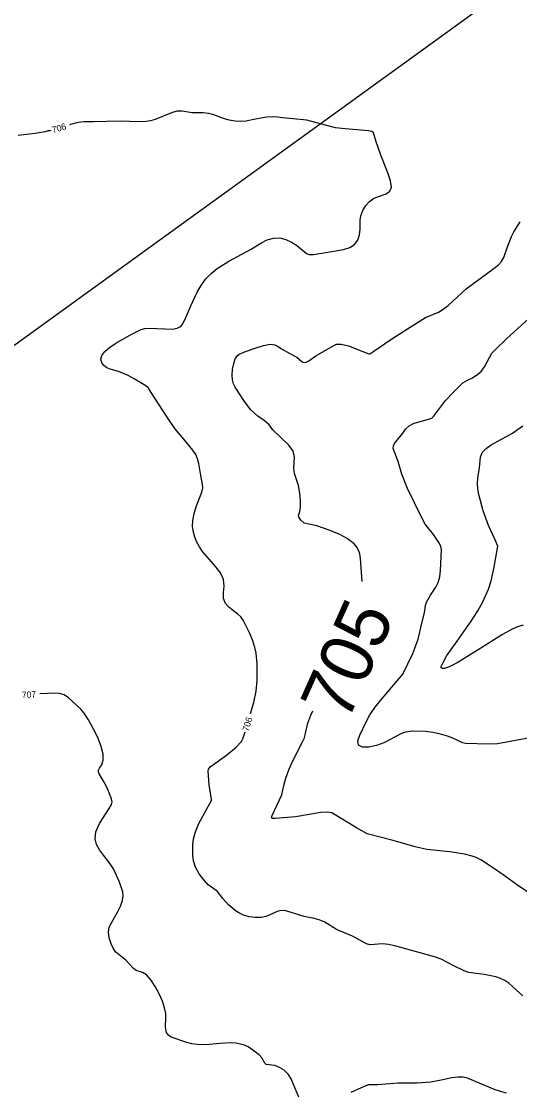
# Model space of a CAD drawing. Extents: x -291892836 to 2945206, y -477993085 to 1832792.
# Drawn here: x 1848702 to 1849014, y 544659 to 545329 of the extents above; entities that cross this region are included whole.
import ezdxf

# ---------------------------------------------------------------- set-up
doc = ezdxf.new("R2010")
doc.units = 0
for name, color, linetype in [('DT_X_Contour_Minor', 7, 'Continuous'), ('DT_X_Terrain_Ground_Line', 7, 'Continuous'), ('Level 19', 7, 'Continuous'), ('SC_Scratch1', 7, 'Continuous')]:
    doc.layers.add(name, color=color, linetype=linetype)

msp = doc.modelspace()

# ---------------------------------------------------------------- linework, layer by layer
at = {"layer": 'DT_X_Contour_Minor'}
for points in [[(1848933.23, 545229.58), (1848931.48, 545234.56), (1848927.12, 545245.56), (1848924.05, 545254.6), (1848922.57, 545259.58), (1848921.44, 545260.36), (1848919.36, 545260.82), (1848904.81, 545262.02), (1848898.8, 545262.72), (1848880.82, 545267.4), (1848872.31, 545268.27), (1848865.59, 545268.96), (1848862.55, 545269.41), (1848859.38, 545269.6), (1848855.87, 545269.38), (1848848.73, 545268.12), (1848842.54, 545266.9), (1848839.37, 545266.7), (1848835.88, 545266.93), (1848832.24, 545267.56), (1848828.75, 545268.52), (1848822.56, 545270.86), (1848819.43, 545271.68), (1848816.02, 545271.99), (1848809, 545272.19), (1848802.71, 545273.11), (1848799.51, 545273.03), (1848796.06, 545272.12), (1848785.87, 545267.93), (1848782.97, 545267.09), (1848780.33, 545266.59), (1848775.27, 545266.46), (1848764.39, 545266.89), (1848755.34, 545266.68), (1848747.31, 545266.39), (1848741.37, 545266.53), (1848737.75, 545266.03), (1848732.95, 545264.75), (1848732.27, 545264.54)], [(1848720.78, 545261.08), (1848719.93, 545260.82), (1848718.9, 545260.78), (1848717.02, 545260.24), (1848710.67, 545259.15), (1848700.11, 545257.83)], [(1848845.57, 544895.69), (1848847.69, 544902.71), (1848849.15, 544909.67), (1848849.67, 544916.5), (1848849.64, 544926.85), (1848849.02, 544933.56), (1848848.27, 544937.12), (1848846.99, 544941.19), (1848845.09, 544945.85), (1848840.98, 544954.16), (1848839.55, 544956.35), (1848837.67, 544957.99), (1848833.97, 544960.73), (1848831.92, 544962.45), (1848829.95, 544964.75), (1848828.74, 544967.72), (1848828.68, 544971.38), (1848828.99, 544975.49), (1848828.61, 544979.73), (1848826.75, 544983.84), (1848823.87, 544987.69), (1848815.55, 544997.3), (1848813.57, 545000.17), (1848811.94, 545003.12), (1848810.67, 545006.21), (1848809.78, 545009.46), (1848809.31, 545012.91), (1848809.4, 545016.69), (1848810.22, 545020.97), (1848811.81, 545025.76), (1848815.09, 545034.44), (1848815.65, 545037.17), (1848815.52, 545039.3), (1848814.5, 545044.95), (1848813.28, 545052.31), (1848812.46, 545055.33), (1848811.26, 545058.03), (1848809.42, 545060.84), (1848803.78, 545067.59), (1848798.23, 545074.28), (1848793.31, 545081.32), (1848783.41, 545096.92), (1848781.72, 545099.55), (1848780.07, 545100.95), (1848772.39, 545105.73), (1848768.96, 545107.58), (1848762.9, 545109.94), (1848757.73, 545111.49), (1848755.5, 545112.42), (1848753.69, 545113.72), (1848752.42, 545115.51), (1848751.95, 545117.68), (1848752.52, 545120.05), (1848754.33, 545122.5), (1848757.27, 545125.03), (1848761.16, 545127.68), (1848770.35, 545133.03), (1848777.05, 545136.39), (1848779.33, 545137), (1848782.05, 545137.1), (1848796.64, 545136.46), (1848799.62, 545137.14), (1848801.84, 545138.27), (1848802.97, 545139.59), (1848804.44, 545142.35), (1848808.19, 545151.21), (1848812.12, 545159.74), (1848814.59, 545163.96), (1848817.47, 545167.89), (1848820.84, 545171.45), (1848824.68, 545174.53), (1848831.96, 545179.05), (1848845.46, 545186.45), (1848852.09, 545190.47), (1848855.94, 545192.42), (1848859.92, 545193.63), (1848863.87, 545193.69), (1848867.65, 545192.76), (1848871.16, 545191.12), (1848874.29, 545189.09), (1848880.63, 545183.96), (1848882.36, 545183.36), (1848884.98, 545183.35), (1848893.99, 545184.75), (1848903.76, 545186.55), (1848907.66, 545187.67), (1848910.67, 545189.5), (1848912.69, 545192.33), (1848913.83, 545195.72), (1848914.26, 545199.12), (1848914.15, 545204.8), (1848914.56, 545207.65), (1848915.83, 545210.84), (1848917.77, 545214), (1848920.08, 545216.62), (1848922.52, 545218.34), (1848925.05, 545219.42), (1848930.48, 545221.29), (1848932.73, 545222.92), (1848933.8, 545225.59), (1848933.23, 545229.58)], [(1848915.38, 544978.41), (1848914.33, 544992.89), (1848913.9, 544995.8), (1848913.24, 544998.07), (1848912.13, 545000.04), (1848910.43, 545001.96), (1848906.12, 545005.39), (1848901.55, 545007.9), (1848894.85, 545010.7), (1848887.1, 545013.3), (1848879.09, 545014.94), (1848877.05, 545016.86), (1848875.73, 545018.93), (1848875.6, 545019.9), (1848876.45, 545022.4), (1848876.86, 545024.99), (1848876.89, 545029.02), (1848876.47, 545033.84), (1848875.6, 545038.6), (1848873.17, 545046.1), (1848872.59, 545049.4), (1848873.11, 545056.42), (1848872.23, 545060.14), (1848869.49, 545063.92), (1848859.75, 545073.3), (1848857.04, 545076.87), (1848854.16, 545079.24), (1848850.23, 545082), (1848848, 545083.86), (1848845.8, 545086.07), (1848841.89, 545091.29), (1848835.88, 545100.18), (1848834.9, 545102.33), (1848834.27, 545104.81), (1848834.07, 545107.81), (1848834.35, 545111.39), (1848835.04, 545115.03), (1848836.04, 545118.05), (1848837.24, 545119.94), (1848838.52, 545120.95), (1848842.5, 545122.56), (1848849.09, 545124.95), (1848853.66, 545126.34), (1848857.78, 545127.09), (1848860.72, 545126.77), (1848862.89, 545125.65), (1848864.99, 545124.19), (1848870.27, 545121.4), (1848874.51, 545119), (1848877.92, 545116.14), (1848879.08, 545115.66), (1848880.44, 545115.78), (1848882.08, 545116.69), (1848886.46, 545119.8), (1848899.23, 545127.11), (1848902.4, 545127.25), (1848906.85, 545126.13), (1848915.82, 545122.54), (1848919.55, 545121.08), (1848920.29, 545121.19), (1848922.72, 545122.74), (1848934.06, 545130.54), (1848946.08, 545138.15), (1848955.12, 545143.93), (1848963.31, 545147.12), (1848966.19, 545148.99), (1848969.25, 545151.31), (1848975.01, 545156.55), (1848980.49, 545161.73), (1848998.14, 545174.69), (1849000.88, 545176.96), (1849002.75, 545179), (1849004.15, 545181.37), (1849006.56, 545188.04), (1849008.97, 545194.68), (1849010.41, 545197.58), (1849014.49, 545203.78)], [(1849026.1, 544881.56), (1849000.18, 544876.68), (1848994.49, 544876.44), (1848980.08, 544876.95), (1848978.25, 544877.33), (1848976.2, 544878.4), (1848972.29, 544880.35), (1848968.85, 544881.63), (1848964.58, 544882.9), (1848959.84, 544883.93), (1848955.01, 544884.53), (1848946.84, 544884.72), (1848942.52, 544884.14), (1848940.13, 544883.2), (1848929.02, 544877.39), (1848924.4, 544875.67), (1848919.72, 544874.67), (1848915.72, 544874.68), (1848913.23, 544875.94), (1848912.8, 544878.57), (1848913.93, 544882.19), (1848917.88, 544890.46), (1848920.36, 544894.87), (1848923.68, 544899.78), (1848928.04, 544905.25), (1848940.93, 544920.34), (1848947.11, 544933.41), (1848949.16, 544938.27), (1848950.53, 544942.24), (1848952.91, 544952.26), (1848954.39, 544958.88), (1848955.13, 544963.47), (1848955.75, 544965.47), (1848958.32, 544969.99), (1848961.56, 544974.99), (1848962.96, 544977.85), (1848964, 544981.28), (1848964.56, 544985.4), (1848965.11, 544998.52), (1848964.65, 545000.58), (1848963.52, 545002.92), (1848960.04, 545007.92), (1848954.97, 545014.36), (1848952.53, 545018.67), (1848943.88, 545036.74), (1848940.4, 545045.8), (1848937.97, 545053.55), (1848934.94, 545061.86), (1848935.05, 545063.43), (1848935.62, 545064.91), (1848940.95, 545071.45), (1848942.52, 545073.86), (1848944.81, 545076.06), (1848948.1, 545077.71), (1848954.99, 545079.61), (1848959.05, 545080.69), (1848960.12, 545081.73), (1848967.71, 545091.8), (1848972.62, 545097.16), (1848978.43, 545103.03), (1848981.44, 545104.7), (1848984.09, 545105.95), (1848987.11, 545107.66), (1848989.9, 545109.96), (1848992.04, 545112.87), (1848996.75, 545121.49), (1848998.87, 545123.9), (1849005.86, 545130.53), (1849022.01, 545145.33)], [(1849016.34, 544951.12), (1849012.73, 544950), (1849009.37, 544948.59), (1849003.3, 544945.15), (1848988.17, 544935.59), (1848974.84, 544927.59), (1848969.95, 544925), (1848966.89, 544924), (1848965.7, 544923.92), (1848965.03, 544924.28), (1848965.02, 544925.17), (1848966.16, 544927.76), (1848968.46, 544931.99), (1848974.97, 544941.11), (1848983.78, 544953.64), (1848987.98, 544960.18), (1848991.07, 544965.76), (1848994.54, 544973.75), (1848996.26, 544978.96), (1848997.88, 544986.34), (1849000.41, 545000.58), (1848998.67, 545004.47), (1848994.63, 545013.53), (1848991.17, 545022.73), (1848988.56, 545033.04), (1848987.91, 545036.46), (1848987.65, 545039.84), (1848987.91, 545043.14), (1848988.92, 545049.69), (1848989.52, 545056.31), (1848990.69, 545059.3), (1848993.03, 545061.87), (1848996.2, 545064.06), (1849009.58, 545071.36), (1849015.98, 545076.08)], [(1848792.49, 544697.71), (1848792.47, 544697.78), (1848792.3, 544699.96), (1848792.62, 544704.7), (1848792.47, 544707.7), (1848791.74, 544711.38), (1848790.39, 544715.61), (1848788.44, 544720.18), (1848785.96, 544724.81), (1848783.21, 544728.95), (1848780.48, 544731.97), (1848778.01, 544733.51), (1848773.96, 544734.81), (1848772.3, 544736.07), (1848767.51, 544741.14), (1848761.23, 544746.18), (1848759.79, 544748.35), (1848758.29, 544751.53), (1848757.07, 544755.24), (1848756.57, 544758.83), (1848757.09, 544761.83), (1848758.43, 544764.57), (1848762.26, 544771.23), (1848764.09, 544775.11), (1848765.38, 544778.64), (1848765.87, 544781.47), (1848765.62, 544783.97), (1848763.47, 544790.12), (1848759.87, 544798.5), (1848757.78, 544801.48), (1848753.43, 544806.93), (1848751.06, 544810.25), (1848749.14, 544813.61), (1848748.21, 544817.27), (1848748.77, 544821.61), (1848751.07, 544826.8), (1848757.04, 544836.2), (1848758.6, 544838.69), (1848758.97, 544840.31), (1848758.46, 544842.24), (1848755.79, 544849.1), (1848753.98, 544852.76), (1848750.7, 544857.94), (1848750.24, 544859.8), (1848751.03, 544861.56), (1848752.4, 544863.63), (1848753.4, 544866.44), (1848753.29, 544870.33), (1848752.06, 544875.14), (1848749.91, 544880.62), (1848747.07, 544886.42), (1848744.04, 544891.82), (1848741.36, 544896.02), (1848739.41, 544898.51), (1848731.64, 544905.58), (1848728.86, 544907.4), (1848725.94, 544908.32), (1848722.82, 544908.5), (1848713.65, 544907.98)], [(1849020.32, 544783.09), (1849013.47, 544787.62), (1849003.75, 544794.67), (1848997.1, 544799.35), (1848989.72, 544804.02), (1848986.93, 544805.49), (1848984.4, 544806.45), (1848979.5, 544807.53), (1848970.43, 544809.05), (1848955.9, 544810.54), (1848948.56, 544812.13), (1848940.66, 544814.43), (1848934.07, 544816.46), (1848918.66, 544820.43), (1848911.99, 544824.21), (1848896.39, 544833.44), (1848893.48, 544833.93), (1848889.67, 544833.64), (1848873.72, 544830.98), (1848861.1, 544829.95), (1848859.44, 544829.92), (1848858.79, 544830.43), (1848859.16, 544831.93), (1848865.13, 544844.87), (1848866.46, 544850.71), (1848867.75, 544855.27), (1848869.6, 544860.54), (1848872.01, 544866.1), (1848878.08, 544877.94), (1848879.29, 544880.6), (1848879.92, 544883.38), (1848881.54, 544889.79), (1848883.24, 544894.69), (1848884.59, 544897.41)], [(1849016.13, 544718.91), (1849011.88, 544722.57), (1849007.22, 544726.7), (1849004.8, 544728.38), (1849002.15, 544729.72), (1848999.09, 544730.76), (1848991.75, 544732.14), (1848982.27, 544733.52), (1848979.35, 544734.45), (1848972.78, 544737.68), (1848964.99, 544741.74), (1848960.85, 544743.38), (1848935.96, 544750.09), (1848931.86, 544751.04), (1848928.26, 544751.46), (1848920.29, 544750.79), (1848918.15, 544751.48), (1848909.35, 544756.23), (1848899.43, 544760.5), (1848892.05, 544764.94), (1848888.58, 544766.51), (1848885.42, 544767.36), (1848879.08, 544768.49), (1848867.74, 544772.03), (1848864.74, 544772.26), (1848862.24, 544771.8), (1848857.69, 544769.69), (1848855.16, 544768.59), (1848852.14, 544767.9), (1848848.54, 544767.89), (1848844.71, 544768.46), (1848841.17, 544769.47), (1848838.28, 544770.77), (1848835.91, 544772.31), (1848831.71, 544775.93), (1848828.15, 544779.84), (1848824.73, 544784.54), (1848819.1, 544788.42), (1848816.27, 544791.48), (1848813.44, 544795.36), (1848811.19, 544799.48), (1848809.95, 544803.36), (1848809.48, 544806.97), (1848809.4, 544813.72), (1848809.81, 544817.33), (1848811.02, 544821.62), (1848813.27, 544826.74), (1848818.26, 544836.02), (1848821.04, 544841.17), (1848821.08, 544842.02), (1848819.66, 544851.11), (1848819.09, 544859.61), (1848819.32, 544860.95), (1848820.25, 544862.29), (1848821.68, 544863.46), (1848830.56, 544869.55), (1848836.54, 544874.69), (1848839.93, 544878.28), (1848840.84, 544879.82), (1848842.13, 544884.19)], [(1848875.74, 544655.32), (1848872.52, 544663.32), (1848871.09, 544666.77), (1848869.23, 544669.75), (1848866.66, 544672.21), (1848863.71, 544674.04), (1848860.84, 544675.12), (1848855.34, 544675.76), (1848854.52, 544676.72), (1848852.68, 544680.07), (1848850.9, 544681.98), (1848846.27, 544685.46), (1848844.03, 544686.81), (1848841.77, 544687.87), (1848839.27, 544688.63), (1848836.34, 544689.12), (1848833.12, 544689.34), (1848826.47, 544689.03), (1848819.63, 544688.34), (1848815.96, 544688.2), (1848812.27, 544688.31), (1848808.77, 544688.75), (1848805.63, 544689.55), (1848795.8, 544693.06), (1848794.16, 544694.17), (1848793.03, 544695.79), (1848792.49, 544697.71)], [(1849005.9, 544657.95), (1848998.71, 544659.98), (1848981.47, 544667.29), (1848978.74, 544667.83), (1848975.35, 544667.86), (1848971.62, 544667.5), (1848964.95, 544666.11), (1848958.52, 544664.74), (1848949.9, 544664.2), (1848937.79, 544664.21), (1848925.11, 544663.2), (1848919.26, 544663.09), (1848914.93, 544661.24), (1848908.29, 544658.27)]]:
    msp.add_lwpolyline(points, dxfattribs=at)
at = {"layer": 'SC_Scratch1'}
msp.add_lwpolyline([(1847508.07, 542206.71), (1846998.91, 543896.83), (1851573.76, 547209.16), (1853501.81, 547291.67), (1855222.4, 545290.6), (1854278.63, 544392.05), (1853736.43, 543286.9), (1848894.08, 540466.94), (1848705.94, 540646.25)], close=True, dxfattribs=at)

# ---------------------------------------------------------------- texts
at = {"layer": 'DT_X_Terrain_Ground_Line'}
for s, p in [('24336GB04.PRF', (1846112.16, 544943.17)), ('ROT=43.3446', (1847031.35, 544779.43))]:
    msp.add_text(s, height=500, rotation=43.34458, dxfattribs=at).set_placement(p)
at = {"layer": 'Level 19'}
for s, height, rotation, p in [('706', 4, 16.77048, (1848721.97, 545259.35)), ('705', 33, 65.91879, (1848906.03, 544889.55)), ('707', 4, 3.23148, (1848702.52, 544905.35)), ('706', 4, 73.24119, (1848844.21, 544884.24))]:
    msp.add_text(s, height=height, rotation=rotation, dxfattribs=at).set_placement(p)

doc.saveas('drawing.dxf')
